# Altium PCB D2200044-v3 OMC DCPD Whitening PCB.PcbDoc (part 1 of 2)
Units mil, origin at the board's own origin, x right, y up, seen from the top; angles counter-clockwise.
Board outline 7000 x 5000 mil, 4 copper layers (Top Layer, Layer 1 (+V), Layer 2 (-V), Bottom Layer), stack 19.156 mil thick; 95 components, 56 nets, 274 pads, 56 vias.
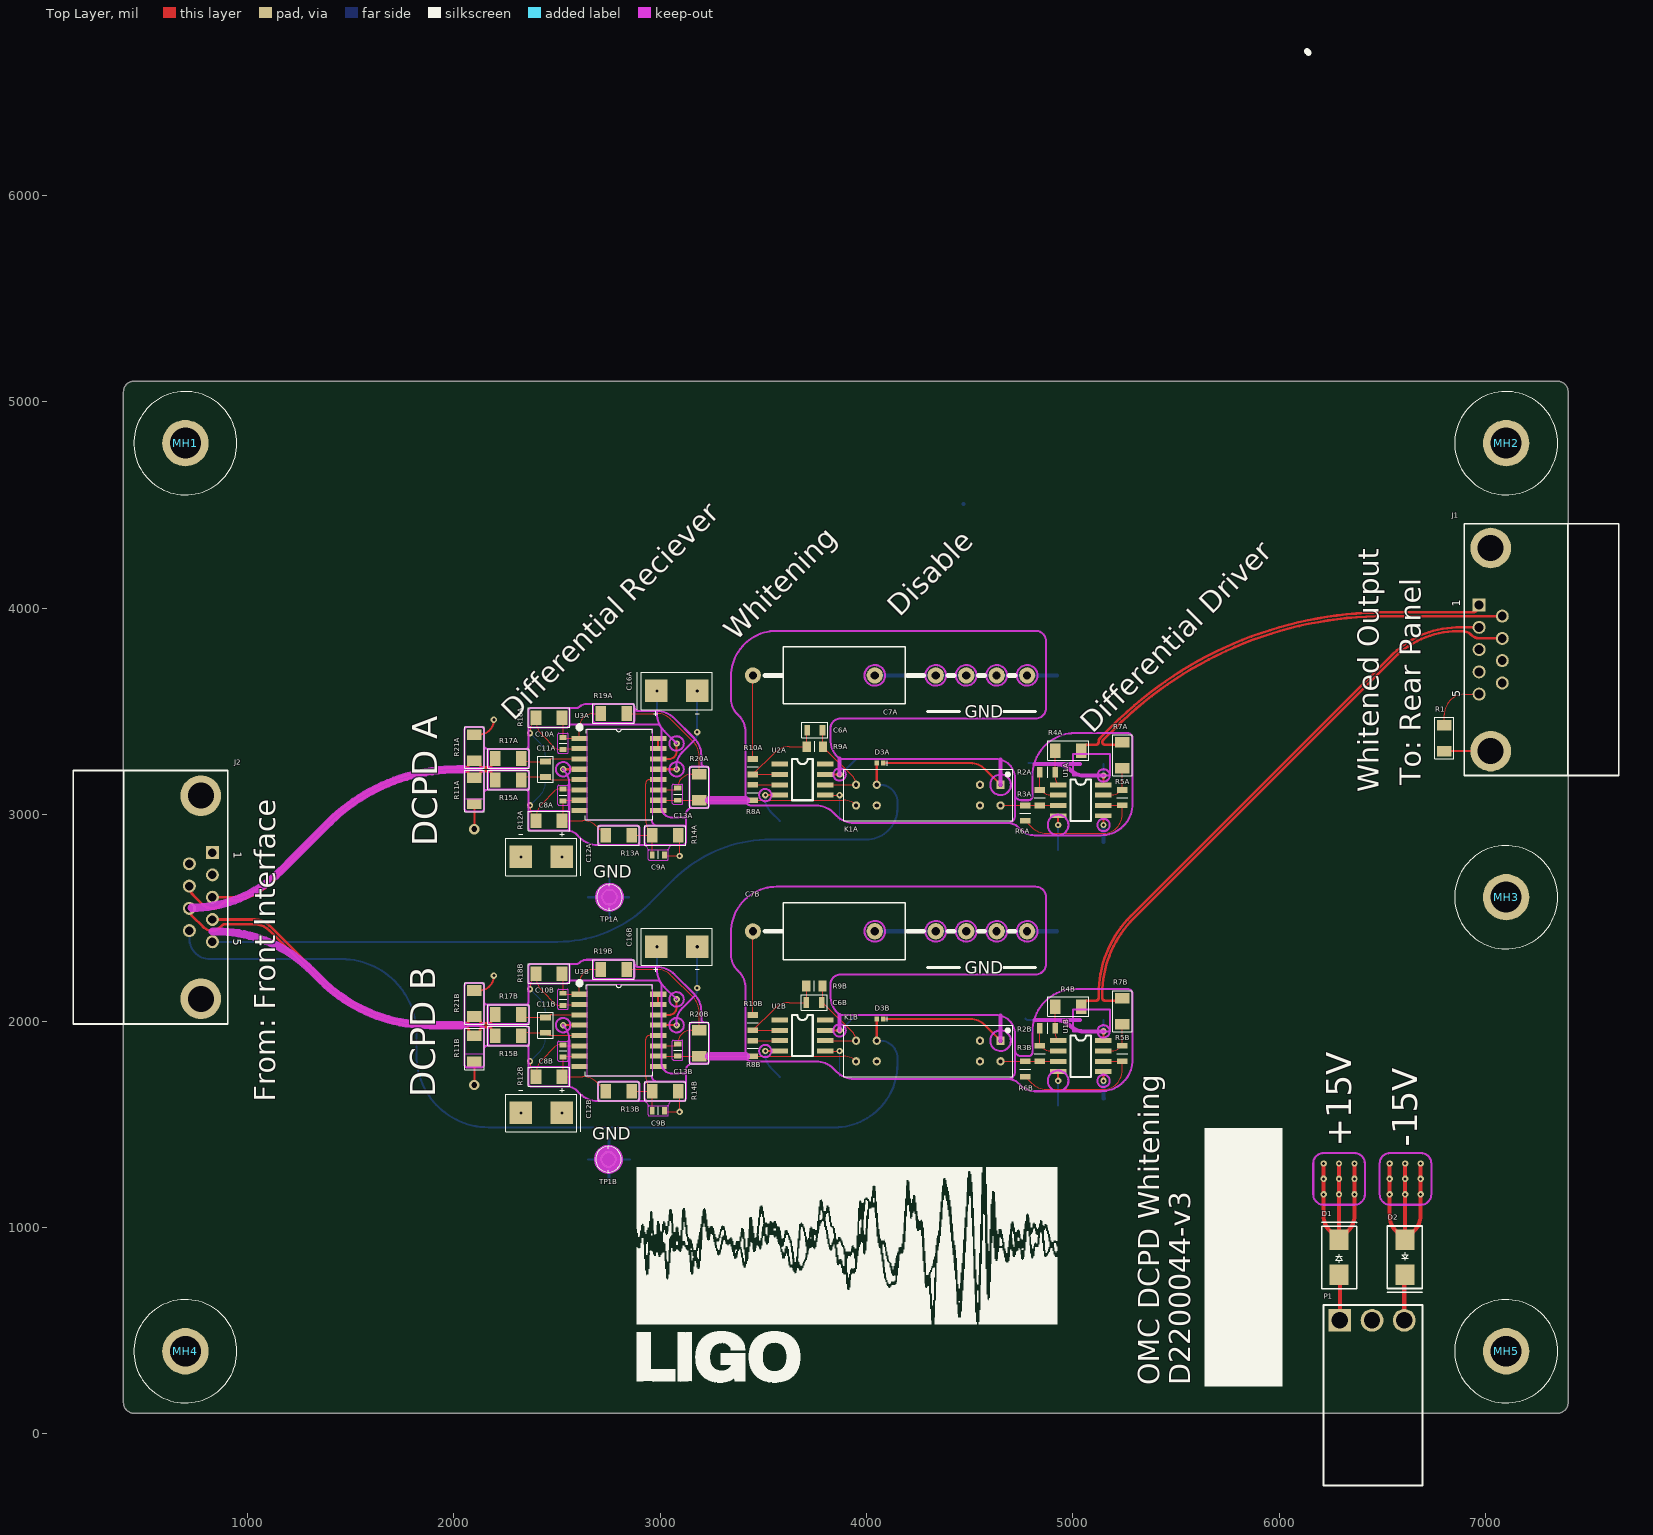
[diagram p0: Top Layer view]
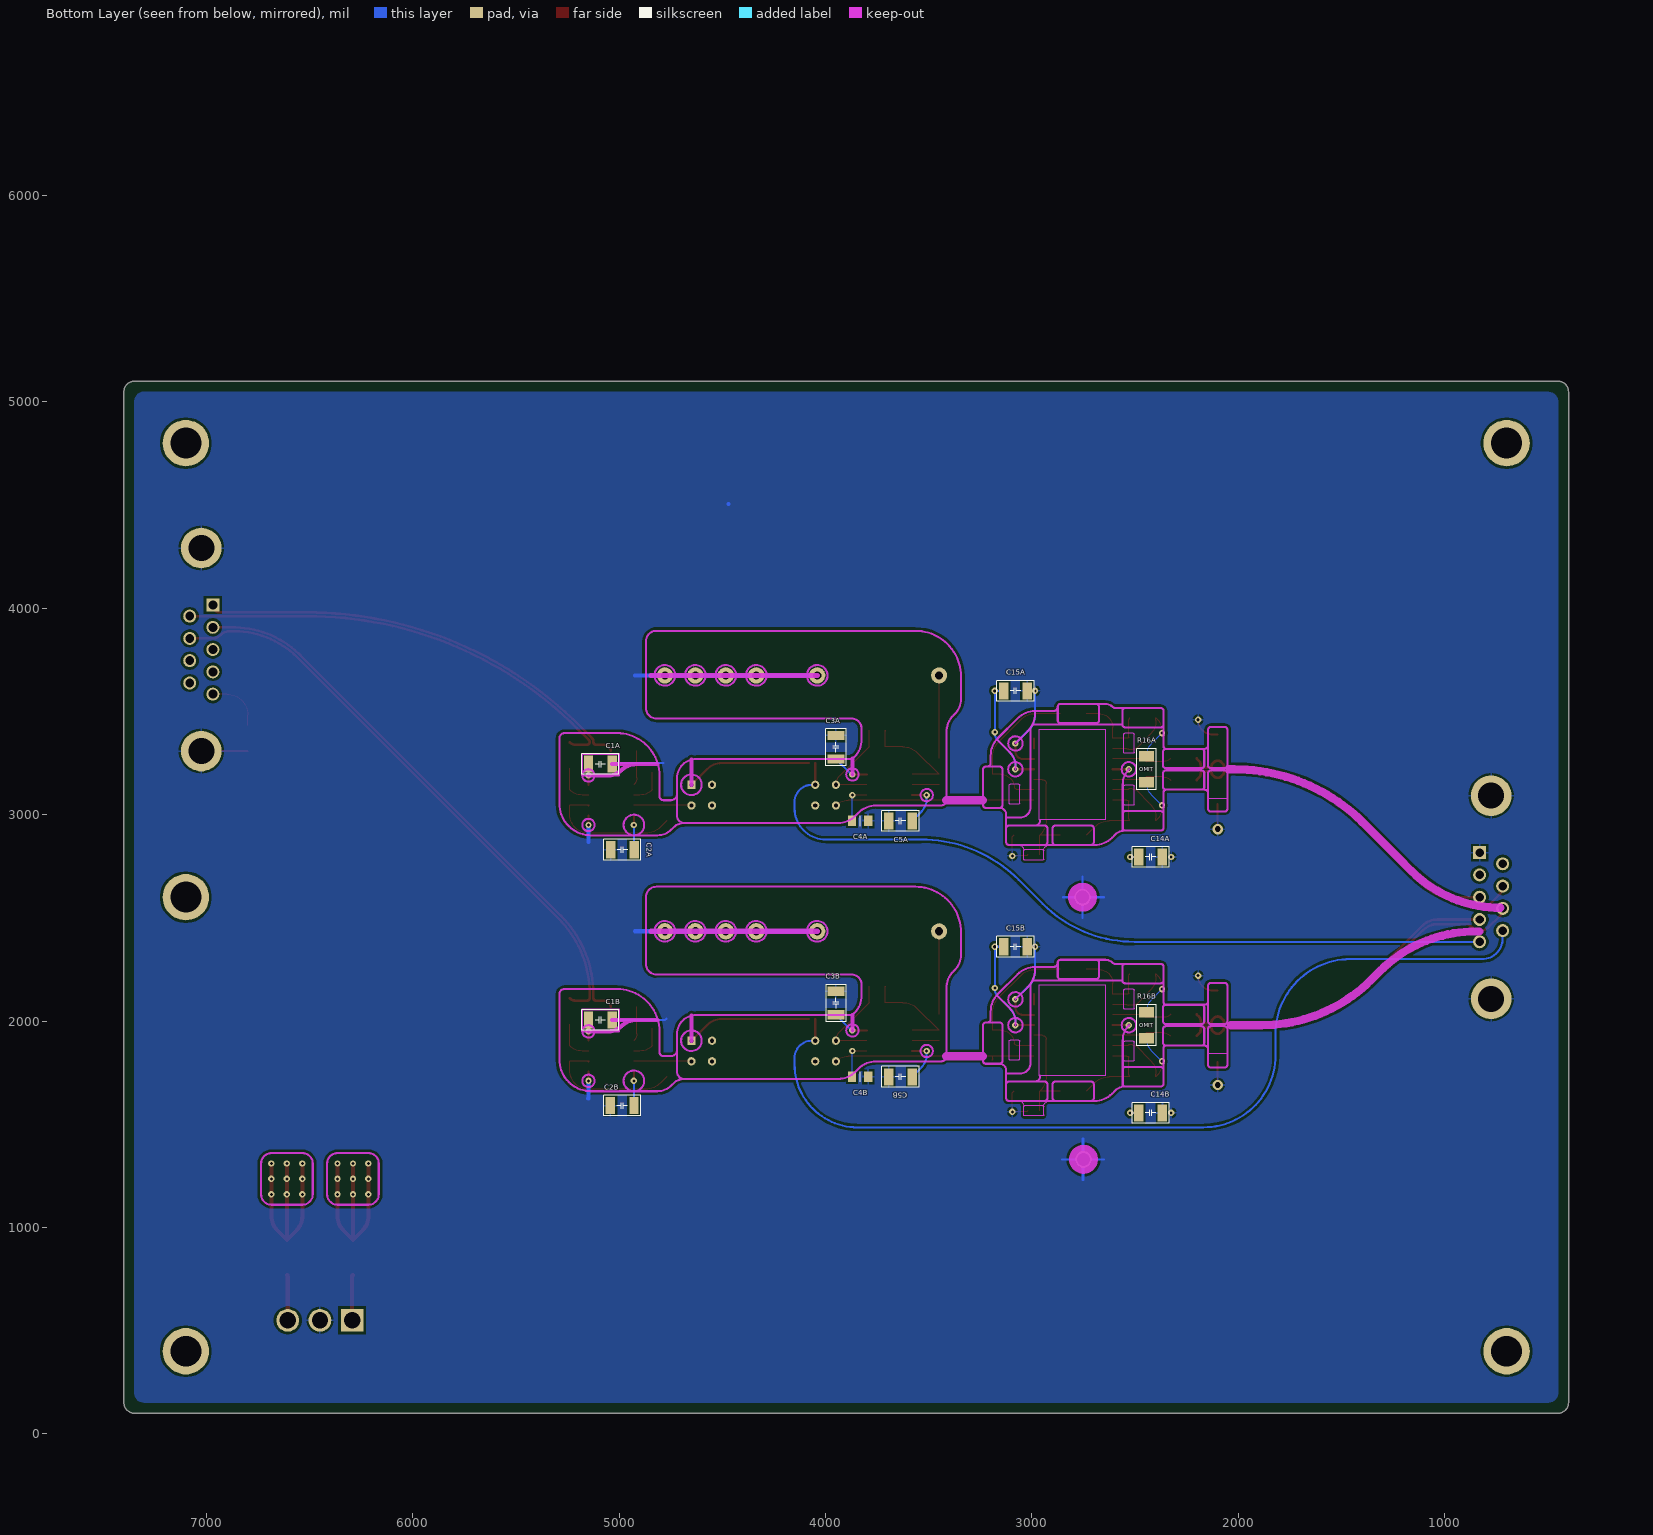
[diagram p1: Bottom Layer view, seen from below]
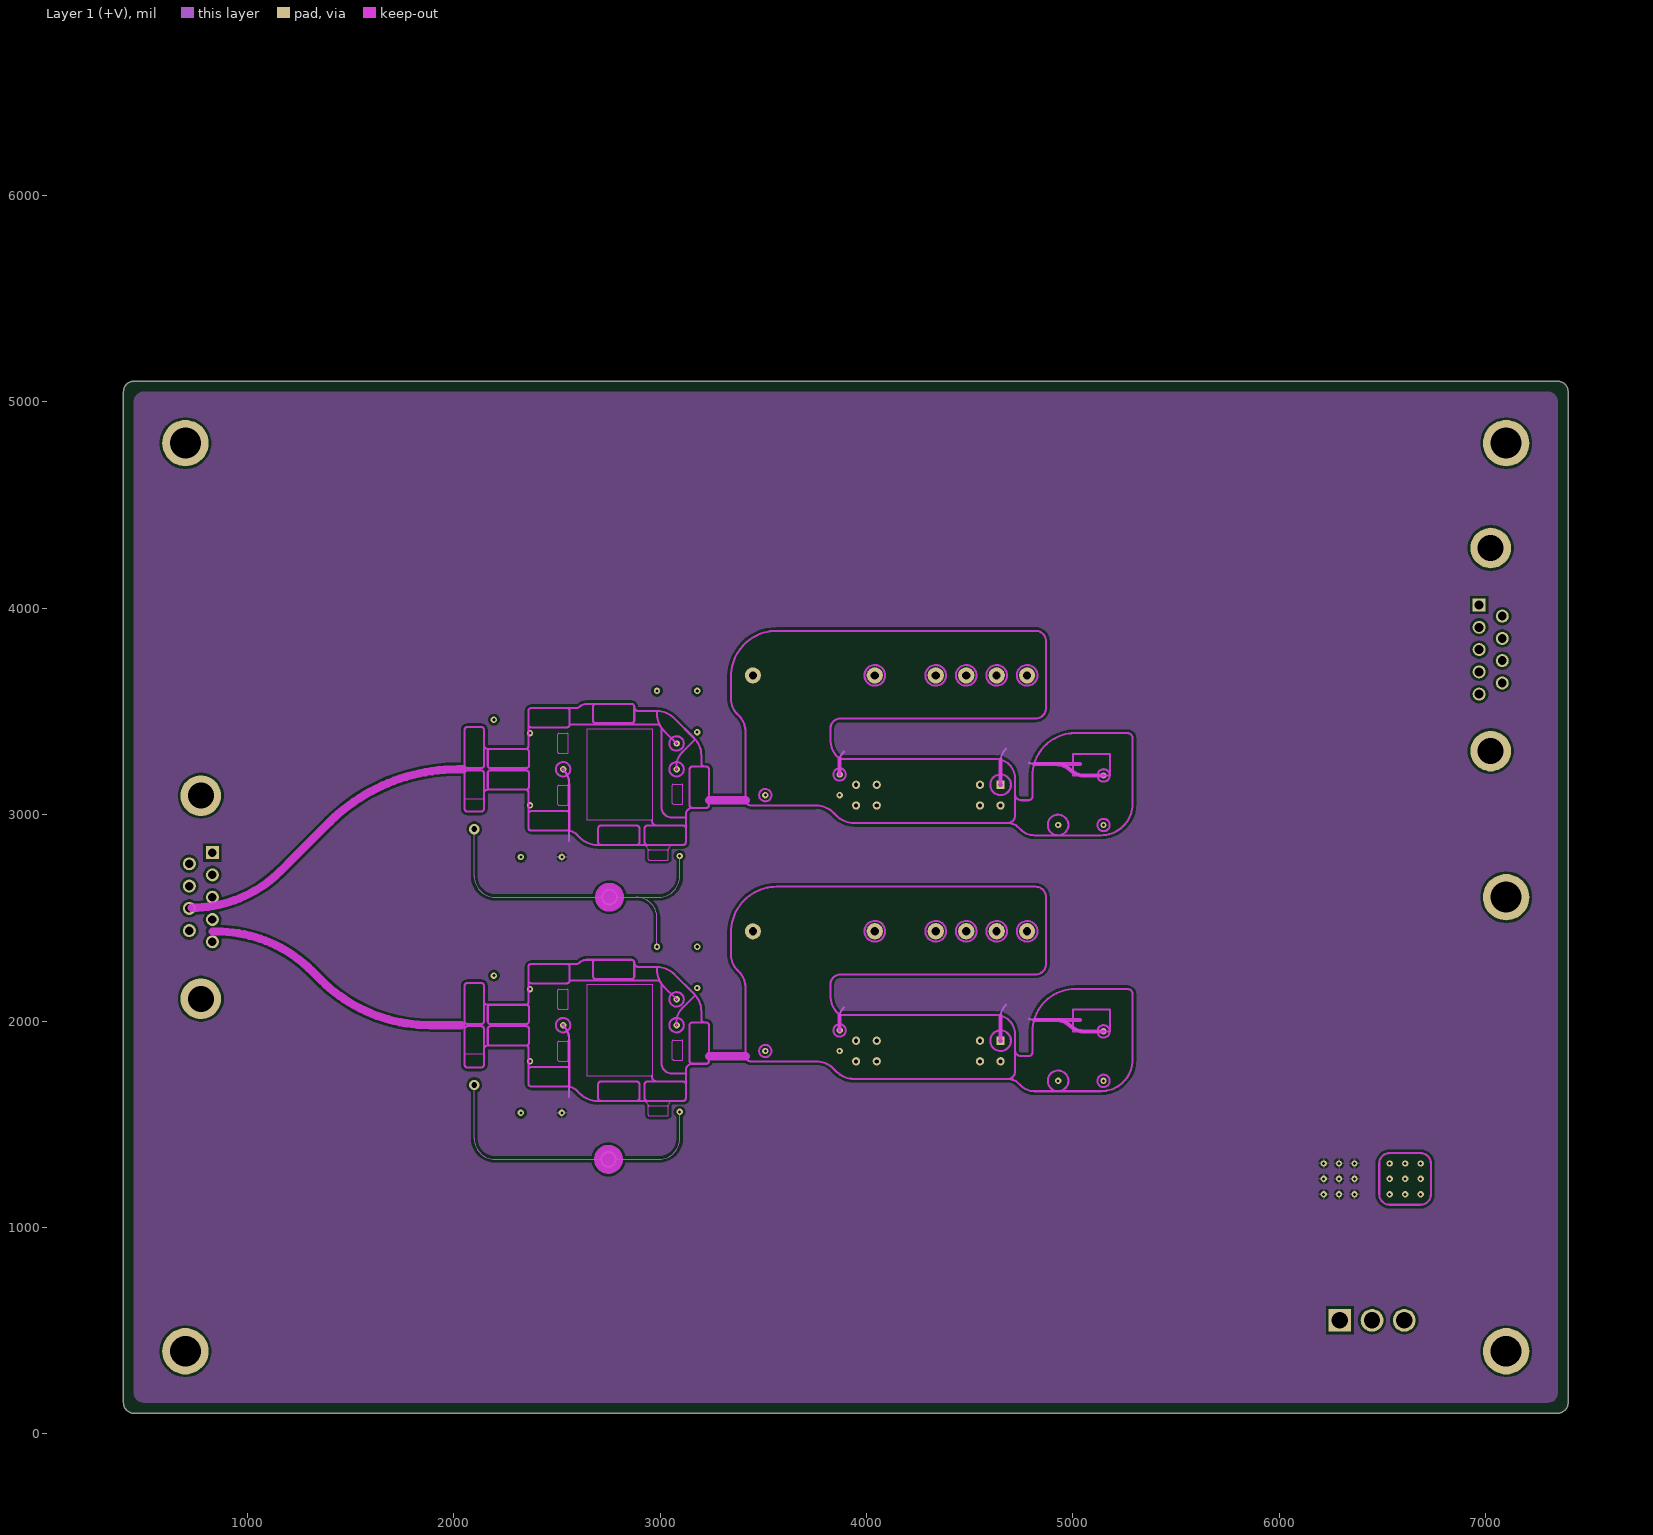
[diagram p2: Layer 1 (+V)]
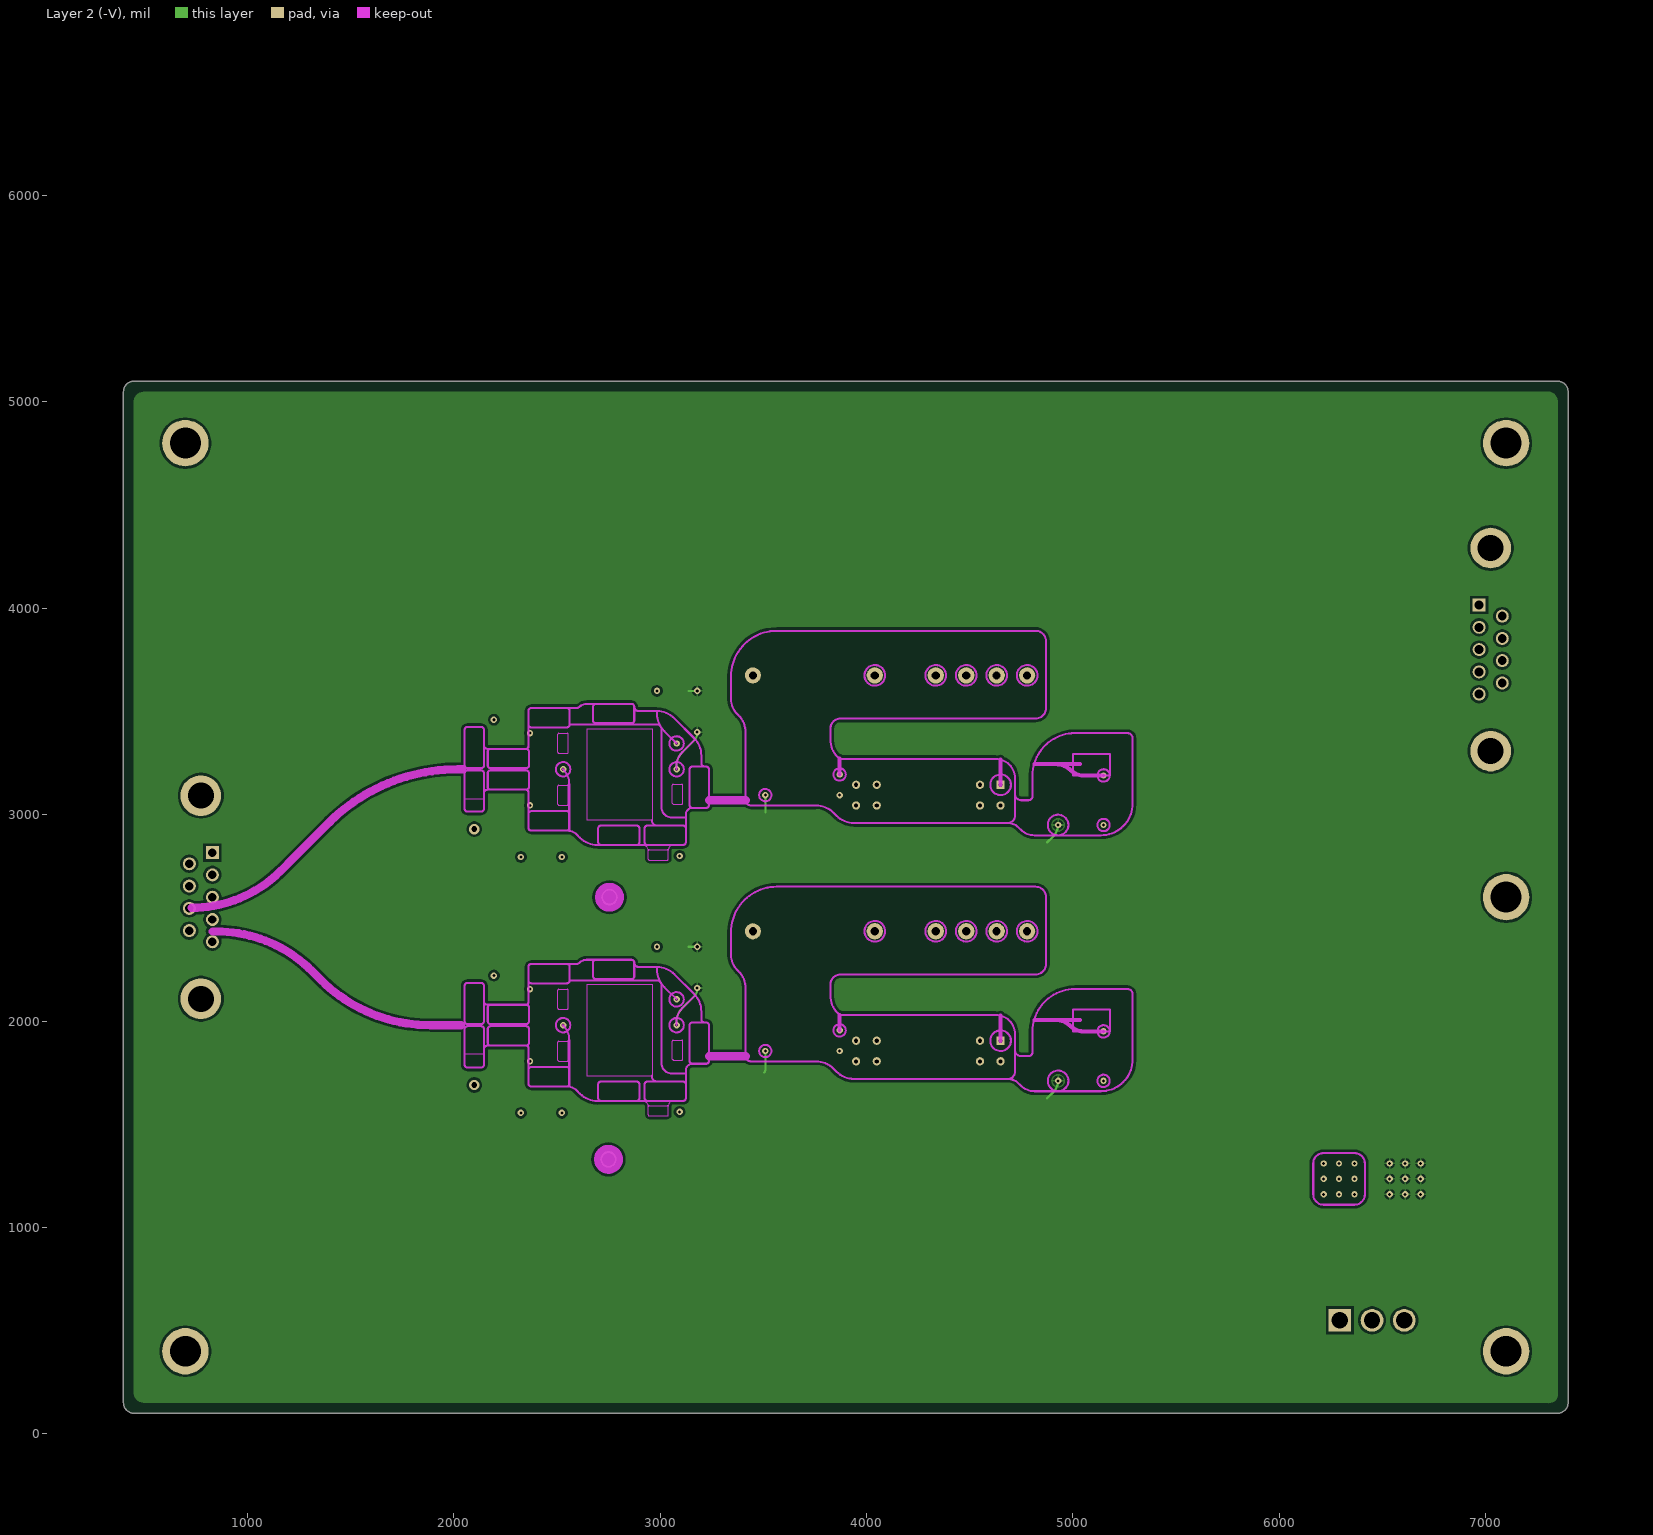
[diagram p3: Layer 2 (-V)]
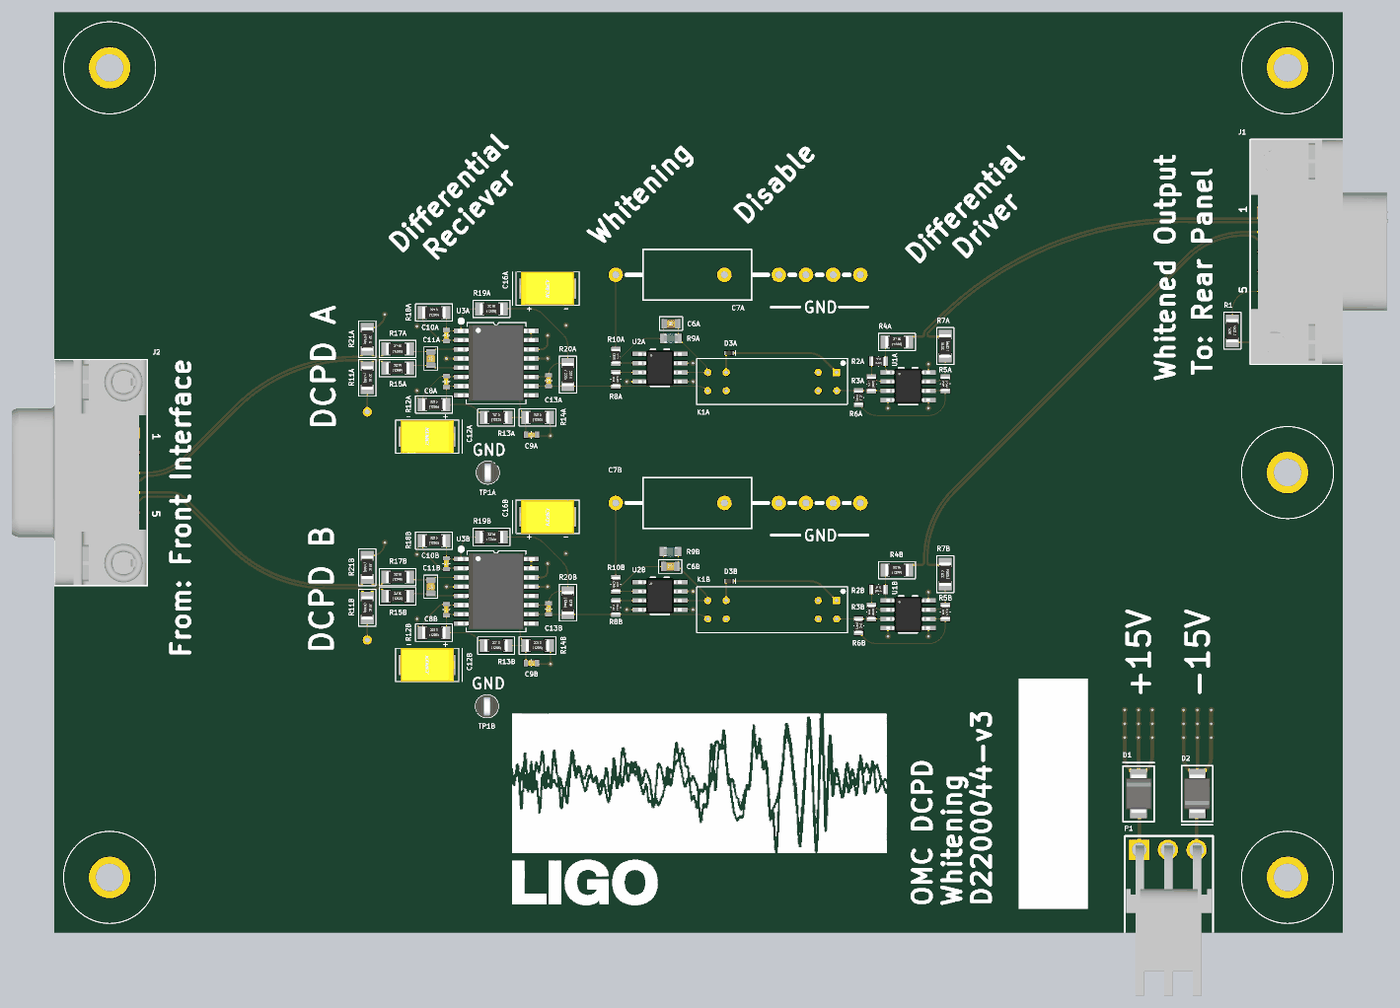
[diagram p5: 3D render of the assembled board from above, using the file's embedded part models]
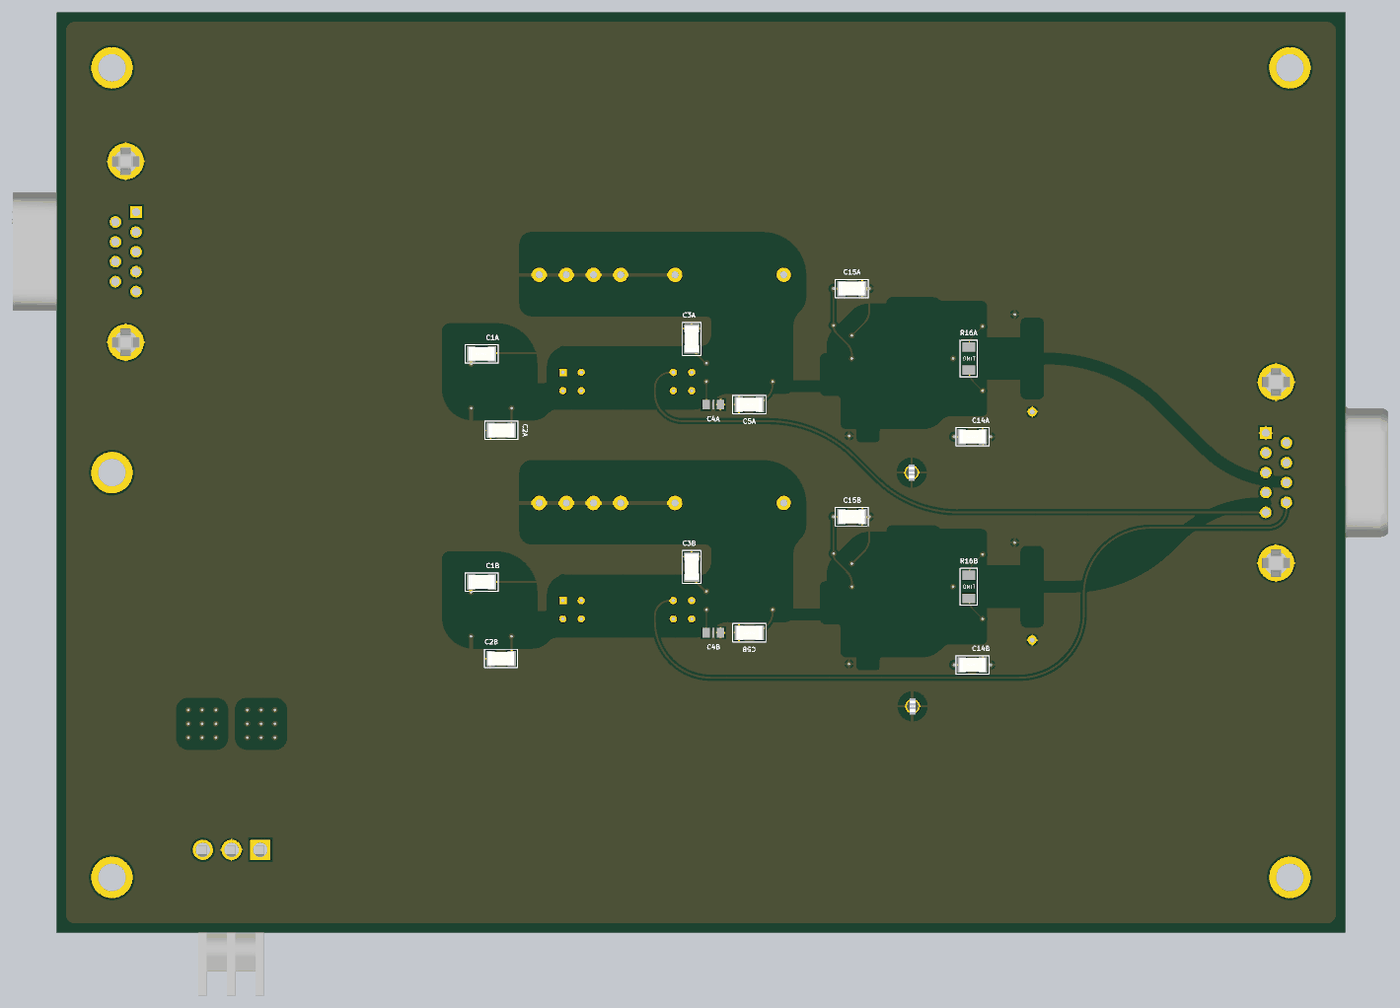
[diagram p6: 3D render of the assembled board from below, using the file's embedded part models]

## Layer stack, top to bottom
Top Solder: solder mask 0.4, Solder Resist, Dk 3.5
Top Layer: signal copper 1.4
Dielectric 2: prepreg 2.8, PP-006, Dk 4.1
Layer 1 (+V): signal copper 1.378
Dielectric 1: core 8, Core-025, Dk 4.6
Layer 2 (-V): signal copper 1.378
Dielectric 3: prepreg 2.8, PP-006, Dk 4.1
Bottom Layer: signal copper 1.4
Bottom Solder: solder mask 0.4, Solder Resist, Dk 3.5

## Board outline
400,5050 cw(c450,5050) 450,5100 7350,5100 cw(c7350,5050) 7400,5050 7400,150 cw(c7350,150) 7350,100 450,100 cw(c450,150) 400,150

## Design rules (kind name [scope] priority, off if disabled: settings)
Clearance [All] p1: gap=2.25 ignorepadtopadclearanceinfootprint=FALSE except(3: Arc-THPad Track-THPad SMDPad-THPad; 5: Arc-Arc Arc-Track Track-Track; 10: SMDPad-Poly; 12: Arc-Fill Arc-Poly Arc-Region Track-Fill Track-Poly Track-Region THPad-Fill THPad-Poly THPad-Region Via-Fill Via-Poly Via-Region Fill-Fill Fill-Poly Fill-Region Poly-Poly Poly-Region Region-Region)
DiffPairsRouting [All] p1: maxlimit=5 minlimit=5 mostfreqgap=5 toplayer_minwidth=12.64 toplayer_maxwidth=12.64 toplayer_prefwidth=12.64 midlayer1_minwidth=9.2 midlayer1_maxwidth=9.2 midlayer1_prefwidth=9.2 midlayer2_minwidth=9.2 midlayer2_maxwidth=9.2 midlayer2_prefwidth=9.2 bottomlayer_minwidth=12.64 bottomlayer_maxwidth=12.64 bottomlayer_prefwidth=12.64 maxuncoupledlength=500
HoleSize [All] p1: absolutevalues=TRUE maxlimit=200 minlimit=14 maxpercent=80.000 minpercent=20.000
MinimumSolderMaskSliver [All] p1: minsoldermaskwidth=3
PlaneConnect [All] p1: planeconnectstyle=Direct reliefexpansion=20 reliefentries=4 reliefconductorwidth=10 reliefairgap=10
PolygonConnect [All] p1: connectstyle=Relief reliefconductorwidth=10 reliefentries=4 polygonreliefangle="90 Angle" airgapwidth=10
RoomDefinition "Whitening B" [InComponentClass('Whitening B')] p1: confinementstyle=ConfineIn formatcopy=TRUE lockcomponents=FALSE outline 2675,1250 2675,1410 2675,1596.72 2936.2,1596.72 3410.41,1596.72 3410.41,2067.23 3676.94,2067.23 3676.94,2129.39 3679.25,2129.39 3679.25,2214.55 4295,2214.55 4295,2295 4455,2295 4455,1992.3 4722.5,1992.3 4722.5,1717.3 3739.59,1717.3 3739.59,1667.3 3739.59,1533.28 3046.87,1533.28 2835,1533.28 2835,1250
RoomDefinition "Whitening A" [InComponentClass('Whitening A')] p2: confinementstyle=ConfineIn formatcopy=TRUE lockcomponents=FALSE outline 2670,2520 2670,2680 2670,2836.72 2936.2,2836.72 3410.41,2836.72 3410.41,3307.23 3674.5,3307.23 3674.5,3459.3 4295,3459.3 4295,3555 4455,3555 4455,3232.3 4722.5,3232.3 4722.5,2957.3 3739.59,2957.3 3739.59,2907.3 3739.59,2773.28 3046.87,2773.28 2830,2773.28 2830,2520
RoomDefinition "Differential-Reciever-Amp D" [InComponentClass('Differential-Reciever-Amp D')] p3: confinementstyle=ConfineIn formatcopy=TRUE lockcomponents=FALSE outline 2020,1610 2020,1770 2040.5,1770 2040.5,2197.5 2349.51,2197.5 2349.51,2289.5 2662.5,2289.5 2662.5,2309.5 2877.5,2309.5 2877.5,2463.05 3264.5,2463.05 3264.5,2227.5 3249.5,2227.5 3249.5,1780.49 3137.5,1780.49 3137.5,1600.5 3046.87,1600.5 3046.87,1533.28 2627.5,1533.28 2627.5,1451.95 2240.5,1451.95 2240.5,1610
RoomDefinition "Differential-Reciever-Amp C" [InComponentClass('Differential-Reciever-Amp C')] p4: confinementstyle=ConfineIn formatcopy=TRUE lockcomponents=FALSE outline 2020,2850 2020,3010 2040.5,3010 2040.5,3437.5 2349.51,3437.5 2349.51,3529.5 2662.5,3529.5 2662.5,3549.5 2877.5,3549.5 2877.5,3703.05 3264.5,3703.05 3264.5,3467.5 3249.5,3467.5 3249.5,3020.49 3137.5,3020.49 3137.5,2840.5 3046.87,2840.5 3046.87,2773.28 2527.5,2773.28 2527.5,2732.5 2322.5,2732.5 2322.5,2850
RoomDefinition "Differential-Driver D" [InComponentClass('Differential-Driver D')] p5: confinementstyle=ConfineIn formatcopy=TRUE lockcomponents=FALSE outline 4730.41,1702.22 4730.41,1832.58 4800.41,1832.58 4800.41,1907.39 4812.22,1907.39 4812.22,2004.59 4865.49,2004.59 4865.49,2129.5 5180.7,2129.5 5180.7,2160.3 5299.7,2160.3 5299.7,1935.3 5279.59,1935.3 5279.59,1777.22 5202.58,1777.22 5202.58,1714.8 5088.17,1714.8 5088.17,1527.5 4883.17,1527.5 4883.17,1702.22
RoomDefinition "Differential-Driver C" [InComponentClass('Differential-Driver C')] p6: confinementstyle=ConfineIn formatcopy=TRUE lockcomponents=FALSE outline 4730.41,2942.22 4730.41,3072.58 4800.41,3072.58 4800.41,3147.39 4812.22,3147.39 4812.22,3244.59 4865.49,3244.59 4865.49,3369.5 5180.7,3369.5 5180.7,3400.3 5299.7,3400.3 5299.7,3175.3 5279.59,3175.3 5279.59,3017.22 5202.58,3017.22 5202.58,2954.8 5087.06,2954.8 5087.06,2767.5 4882.06,2767.5 4882.06,2942.22
RoomDefinition "D2200044-v2 OMC DCPD Whitening" [InComponentClass('D2200044-v2 OMC DCPD Whitening')] p7: confinementstyle=ConfineIn formatcopy=TRUE lockcomponents=FALSE outline 142.95,1971.89 142.95,3228.11 437.5,3228.11 437.5,5062.5 7362.5,5062.5 7362.5,4424.17 7659.02,4424.17 7659.02,3175.83 7362.5,3175.83 7362.5,137.5 6710,137.5 6710,-265 6200,-265 6200,137.5 437.5,137.5 437.5,1971.89
RoutingVias [All] p1: holewidth=28 width=50 viastyle="Through Hole" minholewidth=28 minwidth=50 maxholewidth=28 maxwidth=50
SilkToSilkClearance [All] p1: silktosilkclearance=8
SilkToSolderMaskClearance [IsPad] p1: minsilkscreentomaskgap=2.5 clearancetoexposedcopper=TRUE
SolderMaskExpansion [All] p1: expansion=4 istentingtop=FALSE
Width [All] p1: maxlimit=20 minlimit=5 preferedwidth=10
24 further rules are at their usual default settings.

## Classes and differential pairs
channel class Whitening-v3: "Whitening A" "Whitening B"
channel class Differential-Reciever-Amp: "Differential-Reciever-Amp C" "Differential-Reciever-Amp D"
channel class Differential-Driver: "Differential-Driver C" "Differential-Driver D"
component class "Whitening B": C3B C4B C5B C6B C7B D3B K1B R8B R9B R10B TP1B U2B
component class "Whitening A": C3A C4A C5A C6A C7A D3A K1A R8A R9A R10A TP1A U2A
component class "Differential-Reciever-Amp D": C8B C9B C10B C11B C12B C13B C14B C15B C16B R11B R12B R13B R14B R15B R16B R17B R18B R19B R20B R21B U3B
component class "Differential-Reciever-Amp C": C8A C9A C10A C11A C12A C13A C14A C15A C16A R11A R12A R13A R14A R15A R16A R17A R18A R19A R20A R21A U3A
component class "Differential-Driver D": C1B C2B R2B R3B R4B R5B R6B R7B U1B
component class "Differential-Driver C": C1A C2A R2A R3A R4A R5A R6A R7A U1A
component class "D2200044-v2 OMC DCPD Whitening": D1 D2 J1 J2 MH1 MH2 MH3 MH4 MH5 P1 R1
differential pair "DCPD In B": +"DCPD In B_p" -"DCPD In B_n"
differential pair "DCPD In A": +"DCPD In A_p" -"DCPD In A_n"
differential pair "OMC A - DCPD B": +"OMC A - DCPD B_p" -"OMC A - DCPD B_n"
differential pair "OMC A - DCPD A": +"OMC A - DCPD A_p" -"OMC A - DCPD A_n"

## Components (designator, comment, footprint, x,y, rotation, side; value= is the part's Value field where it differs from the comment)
C1A "0.1 uF" "1206 (3216 Metric) CAP" 5091.5,3245 r180 bottom (schematic designator C1)
C1B "0.1 uF" "1206 (3216 Metric) CAP" 5091.5,2005 r180 bottom (schematic designator C1)
C2A "0.1 uF" "1206 (3216 Metric) CAP" 4984.56,2830 r0 bottom (schematic designator C2)
C2B "0.1 uF" "1206 (3216 Metric) CAP" 4985.67,1590 r0 bottom (schematic designator C2)
C3A "0.1 uF" "1206 (3216 Metric) CAP" 3950,3326.89 r90 bottom (schematic designator C3)
C3B "0.1 uF" "1206 (3216 Metric) CAP" 3950,2086.89 r90 bottom (schematic designator C3)
C4A "0805 OMIT" "2012[0805] - NF" 3832.6,2969.8 r180 bottom (schematic designator C4)
C4B "0805 OMIT" "2012[0805] - NF" 3832.6,1729.8 r180 bottom (schematic designator C4)
C5A "0.1 uF" "1206 (3216 Metric) CAP" 3637.09,2969.8 r0 bottom (schematic designator C5)
C5B "0.1 uF" "1206 (3216 Metric) CAP" 3637.09,1729.8 r0 bottom (schematic designator C5)
C6A "10p +/-0.25pF" "0805 CAP" 3750,3409.8 r0 top (schematic designator C6)
C6B "10p +/-0.25pF" "0805 CAP" 3746.06,2089.8 r0 top (schematic designator C6)
C7A "10uF 1% (PC)" "CAP FILM AXIAL (MULTI LENGTH)" 3892.91,3675 r0 top (schematic designator C7)
C7B "10uF 1% (PC)" "CAP FILM AXIAL (MULTI LENGTH)" 3892.91,2435 r0 top (schematic designator C7)
C8A "4.7 pF (+/-0.05pF)(TF)" "0603 CAP" 2530,3095 r270 top (schematic designator C8)
C8B "4.7 pF (+/-0.05pF)(TF)" "0603 CAP" 2530,1855 r270 top (schematic designator C8)
C9A "4.7 pF (+/-0.05pF)(TF)" "0603 CAP" 2991.54,2805 r0 top (schematic designator C9)
C9B "4.7 pF (+/-0.05pF)(TF)" "0603 CAP" 2991.54,1565 r0 top (schematic designator C9)
C10A "4.7 pF (+/-0.05pF)(TF)" "0603 CAP" 2530,3345 r90 top (schematic designator C10)
C10B "4.7 pF (+/-0.05pF)(TF)" "0603 CAP" 2530,2105 r90 top (schematic designator C10)
C11A "1800pF 50V (1%)(PPS)" "0805 CAP" 2445,3220 r270 top (schematic designator C11)
C11B "1800pF 50V (1%)(PPS)" "0805 CAP" 2445,1980 r270 top (schematic designator C11)
C12A "10uF" "2917 (7343 Metric)" 2425,2795 r0 top (schematic designator C12)
C12B "10uF" "2917 (7343 Metric)" 2425,1555 r0 top (schematic designator C12)
C13A "4.7 pF (+/-0.05pF)(TF)" "0603 CAP" 3085,3099.53 r270 top (schematic designator C13)
C13B "4.7 pF (+/-0.05pF)(TF)" "0603 CAP" 3085,1859.53 r270 top (schematic designator C13)
C14A "0.1 uF" "1206 (3216 Metric) CAP" 2425,2795 r180 bottom (schematic designator C14)
C14B "0.1 uF" "1206 (3216 Metric) CAP" 2425,1555 r180 bottom (schematic designator C14)
C15A "0.1 uF" "1206 (3216 Metric) CAP" 3080,3600 r180 bottom (schematic designator C15)
C15B "0.1 uF" "1206 (3216 Metric) CAP" 3080,2360 r180 bottom (schematic designator C15)
C16A "10uF" "2917 (7343 Metric)" 3080,3600 r180 top (schematic designator C16)
C16B "10uF" "2917 (7343 Metric)" 3080,2360 r180 top (schematic designator C16)
D1 "50V 1A" "DO-214AA, SMB" 6290,855 r90 top
D2 "50V 1A" "DO-214AA, SMB" 6610,855 r270 top
D3A "1N4148" "0402 Diode" 4065.75,3249.8 r0 top (schematic designator D3)
D3B "1N4148" "0402 Diode" 4065.75,2009.8 r0 top (schematic designator D3)
J1 "D9F RA" "D9F 90DEG" 7025,3800 r90 top
J2 "D9M 90DEG" "D9M 90DEG" 775,2600 r270 top locked
K1A "Relay SPDT" "Relay SPDT 0.25A 12V" 4300,3094.8 r180 top (schematic designator K1)
K1B "Relay SPDT" "Relay SPDT 0.25A 12V" 4300,1854.8 r180 top (schematic designator K1)
MH1 "Mounting Hole #6" "Mounting Hole #6" 700,4800 r0 top
MH2 "Mounting Hole #6" "Mounting Hole #6" 7100,4800 r0 top
MH3 "Mounting Hole #6" "Mounting Hole #6" 7100,2600 r0 top
MH4 "Mounting Hole #6" "Mounting Hole #6" 700,400 r0 top
MH5 "Mounting Hole #6" "Mounting Hole #6" 7100,400 r0 top
P1 "HDR 3x1 R/A" "MOLEX HDR1X3 R/A" 6450,550 r0 top locked
R1 "0 Ohm" "1206 Resistor" 6800,3370.99 r90 top
R2A "5k (0.05%)" "0805 Resistor" 4877.4,3205 r0 top (schematic designator R2)
R2B "5k (0.05%)" "0805 Resistor" 4877.4,1965 r0 top (schematic designator R2)
R3A "5k (0.05%)" "0805 Resistor" 4840,3082.2 r90 top (schematic designator R3)
R3B "5k (0.05%)" "0805 Resistor" 4840,1842.2 r90 top (schematic designator R3)
R4A "0 Ohm" "1206 Resistor" 4977.99,3310 r0 top (schematic designator R4)
R4B "0 Ohm" "1206 Resistor" 4977.99,2070 r0 top (schematic designator R4)
R5A "5k (0.05%)" "0805 Resistor" 5240,3082.4 r90 top (schematic designator R5)
R5B "5k (0.05%)" "0805 Resistor" 5240,1842.4 r90 top (schematic designator R5)
R6A "5k (0.05%)" "0805 Resistor" 4770,3007.4 r270 top (schematic designator R6)
R6B "5k (0.05%)" "0805 Resistor" 4770,1767.4 r270 top (schematic designator R6)
R7A "0 Ohm" "1206 Resistor" 5240.2,3287.8 r90 top (schematic designator R7)
R7B "0 Ohm" "1206 Resistor" 5240.2,2047.8 r90 top (schematic designator R7)
R8A "1k (0.01%)" "0805 Resistor" 3450,3107.4 r90 top (schematic designator R8)
R8B "1k (0.01%)" "0805 Resistor" 3450,1867.4 r90 top (schematic designator R8)
R9A "14.3k (0.1%)" 2012[0805] 3750,3329.8 r0 top (schematic designator R9)
R9B "14.3k (0.1%)" 2012[0805] 3748.03,2169.8 r0 top (schematic designator R9)
R10A "1.6k (0.05%)" "0805 Resistor" 3450,3232.2 r270 top (schematic designator R10)
R10B "1.6k (0.05%)" "0805 Resistor" 3450,1992.2 r270 top (schematic designator R10)
R11A "100k (0.01%)" "1206 Resistor" 2100,3115 r270 top (schematic designator R11)
R11B "100k (0.01%)" "1206 Resistor" 2100,1865.01 r270 top (schematic designator R11)
R12A "1k (0.01%)" "1206 Resistor" 2462.01,2970 r0 top (schematic designator R12)
R12B "1k (0.01%)" "1206 Resistor" 2462.01,1730 r0 top (schematic designator R12)
R13A "3.01k (0.01%)" "1206 Resistor" 2800,2900 r0 top (schematic designator R13)
R13B "3.01k (0.01%)" "1206 Resistor" 2800,1660 r0 top (schematic designator R13)
R14A "1.5k (0.01%)" "1206 Resistor" 3025,2900 r0 top (schematic designator R14)
R14B "1.5k (0.01%)" "1206 Resistor" 3025,1660 r0 top (schematic designator R14)
R15A "1k (0.01%)" "1206 Resistor" 2265,3168 r0 top (schematic designator R15)
R15B "1k (0.01%)" "1206 Resistor" 2265,1928 r0 top (schematic designator R15)
R16A "OMIT" "1206 Resistor - OMIT" 2445,3220 r270 bottom (schematic designator R16)
R16B "OMIT" "1206 Resistor - OMIT" 2445,1980 r270 bottom (schematic designator R16)
R17A "1k (0.01%)" "1206 Resistor" 2265,3272 r0 top (schematic designator R17)
R17B "1k (0.01%)" "1206 Resistor" 2265,2032 r0 top (schematic designator R17)
R18A "1k (0.01%)" "1206 Resistor" 2462.01,3470 r0 top (schematic designator R18)
R18B "1k (0.01%)" "1206 Resistor" 2462.01,2230 r0 top (schematic designator R18)
R19A "3.01k (0.01%)" "1206 Resistor" 2775,3490 r0 top (schematic designator R19)
R19B "3.01k (0.01%)" "1206 Resistor" 2775,2250 r0 top (schematic designator R19)
R20A "1.5k (0.01%)" "1206 Resistor" 3190,3132.99 r270 top (schematic designator R20)
R20B "1.5k (0.01%)" "1206 Resistor" 3190,1892.99 r270 top (schematic designator R20)
R21A "100k (0.01%)" "1206 Resistor" 2100,3325 r270 top (schematic designator R21)
R21B "100k (0.01%)" "1206 Resistor" 2100,2085 r270 top (schematic designator R21)
TP1A "Black" "Test Point Tall - Black" 2755,2600 r0 top (schematic designator TP1)
TP1B "Black" "Test Point Tall - Black" 2750,1330 r0 top (schematic designator TP1)
U1A "AD8672" "SOIC-8 (0.154\", 3.90mm Width)" 5038.58,3069.8 r0 top (schematic designator U1)
U1B "AD8672" "SOIC-8 (0.154\", 3.90mm Width)" 5038.58,1829.8 r0 top (schematic designator U1)
U2A "OP37" "SOIC-8 (0.154\", 3.90mm Width)" 3690,3169.8 r0 top (schematic designator U2)
U2B "OP37" "SOIC-8 (0.154\", 3.90mm Width)" 3690,1929.8 r0 top (schematic designator U2)
U3A "LT1125CS" "SOIC-16W (0.295\", 7.50mm Width)" 2800,3195 r0 top (schematic designator U3)
U3B "LT1125CS" "SOIC-16W (0.295\", 7.50mm Width)" 2800,1955 r0 top (schematic designator U3)

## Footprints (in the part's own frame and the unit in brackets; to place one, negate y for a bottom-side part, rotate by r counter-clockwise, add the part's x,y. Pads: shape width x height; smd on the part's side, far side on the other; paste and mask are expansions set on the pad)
"0402 Diode" [mm]
  rect 0.5x0.6 smd: 1(-0.4,0) 2(0.4,0)
  silkscreen extent 0.89,-0.3 0.89,0.3, body extent -0.5,-0.3 0.5,0.3, height 0.5
"0603 CAP" [mm]
  rect 0.6x0.9 smd: 1(-0.75,0) 2(0.75,0)
  silkscreen extent 0,-0.48 0,0.48, body extent -0.8,-0.4 0.8,0.4, height 0.8
"0805 CAP" [mm]
  rect 0.7x1.3 smd: 1(-0.95,0) 2(0.95,0)
  silkscreen extent -1.6,-0.94 1.6,0.94, body extent -1,-0.62 1,0.63, height 0.9
"0805 Resistor" [mm]
  rect 0.7x1.3 smd: 1(-0.95,0) 2(0.95,0)
  silkscreen extent 0,-0.69 0,0.69, body extent -1,-0.62 1,0.63, height 0.45
"1206 (3216 Metric) CAP" [mm] "Chip Capacitor; Body 3.2 x 1.6 mm (LxW typ)"
  rect 1.15x2.1 smd: 1(-1.45,0) 2(1.45,0)
  silkscreen extent -2.29,-1.27 2.29,1.27, body extent -1.8,-0.93 1.8,0.97, height 1.11
"1206 Resistor" [mm]
  rect 1.3x1.8 smd: 1(-1.6,0) 2(1.6,0)
  silkscreen extent -2.54,-1.19 2.54,1.19, body extent -1.6,-0.8 1.6,0.8, height 0.55
"1206 Resistor - OMIT" [mm]
  rect 1.3x1.8 smd: 1(-1.6,0) 2(1.6,0)
  silkscreen extent -2.54,-1.19 2.54,1.19
2012[0805] [mm] "Chip Resistor; Body 2.0 x 1.3 mm (LxW typ)"
  rect 1x1.3 smd: 1(-1,0) 2(1,0)
  silkscreen extent 0,-0.64 0,0.64, body extent -1,-0.62 1,0.63, height 0.46
"2012[0805] - NF" [mm] "Chip Resistor; Body 2.0 x 1.3 mm (LxW typ)"
  rect 1x1.3 smd: 1(-1,0) 2(1,0)
  silkscreen extent 0,-0.64 0,0.64
"2917 (7343 Metric)" [mm]
  rect 2.77x2.77 smd: 1(2.528,0) 2(-2.527,0)
  silkscreen extent -4.37,-2.3 4.83,3.05, body extent -3.8,-2.3 3.8,2.3, height 4.31
"CAP FILM AXIAL (MULTI LENGTH)" [mil]
  round 78 hole 39.37: 1(-442.91,0)
  round 79 hole 39.37: 2(147.64,0) 2(442.91,0) 2(590.55,0) 2(738.19,0) 2(885.83,0)
  silkscreen extent -384,-138 827,138, body extent -276,-128 276,128, height 285
"D9F 90DEG" [mm]
  rect 1.6x1.6 hole 1.1: 1(5.486,1.422)
  round 1.6 hole 1.1: 2(2.743,1.422) 3(0,1.422) 4(-2.743,1.422) 5(-5.486,1.422) 6(4.115,-1.422) 7(1.372,-1.422) 8(-1.365,-1.422) 9(-4.115,-1.422)
  round 5 hole 3.2: 10(-12.497,0) 11(12.497,0)
  silkscreen extent -15.5,-15.75 15.5,3.25, body extent -15.49,-15.71 15.49,3.18, height 12.56
"D9M 90DEG" [mm]
  rect 1.6x1.6 hole 1.04: 1(-5.486,1.422)
  round 1.6 hole 1.04: 2(-2.743,1.422) 3(0,1.422) 4(2.743,1.422) 5(5.486,1.422) 6(-4.115,-1.422) 7(-1.372,-1.422) 8(1.372,-1.422) 9(4.115,-1.422)
  round 5 hole 3.2: 10(-12.497,0) 11(12.497,0)
  silkscreen extent -15.6,-15.7 15.6,3.3, body extent -15.52,-15.4 15.51,3.2, height 12.56
"DO-214AA, SMB" [mm]
  rect 2.5x2.3 smd: 1(-2.15,0) 2(2.15,0)
  silkscreen extent -3.86,-2.18 4.32,2.13, body extent -2.7,-1.83 2.7,1.77, height 2.32
"MOLEX HDR1X3 R/A" [mil]
  rect 110x110 hole 79: 1(-156,0)
  round 110 hole 79: 2(0,0) 3(156,0)
  silkscreen extent -235,-800 245,75, body extent -226,-793 236,23, height 394
"Mounting Hole #6" [mil]
  round 225 hole 150: 1(0,0)
  silkscreen extent -250,-250 250,250
"Relay SPDT 0.25A 12V" [mil] "RELAY REED SPDT 250MA 12V"
  rect 40x40 hole 20: 1(-350,-50)
  round 40 hole 20: 2(-250,-50) 3(250,-50) 4(350,-50) 5(350,50) 6(250,50) 7(-250,50) 8(-350,50)
  silkscreen extent -410,-125 410,125, body extent -410,-125 410,125, height 300
"SOIC-8 (0.154\", 3.90mm Width)" [mil] "Small Outline 8-pin IC"
  rect 80x24 smd: 1(-110,75) 2(-110,25) 3(-110,-25) 4(-110,-75) 5(110,-75) 6(110,-25) 7(110,25) 8(110,75)
  silkscreen extent -50,-100 50,100, body extent -118,-96 118,96, height 67
"SOIC-16W (0.295\", 7.50mm Width)" [mm]
  rect 2x0.63 smd: 1(-4.85,4.445) 2(-4.85,3.175) 3(-4.85,1.905) 4(-4.85,0.635) 5(-4.85,-0.635) 6(-4.85,-1.905) 7(-4.85,-3.175) 8(-4.85,-4.445) 9(4.85,-4.445) 10(4.85,-3.175) 11(4.85,-1.905) 12(4.85,-0.635) 13(4.85,0.635) 14(4.85,1.905) 15(4.85,3.175) 16(4.85,4.445)
  silkscreen extent -5.07,-5.59 4.13,6.05, body extent -5.31,-5.25 5.31,5.25, height 2.66
"Test Point Tall - Black" [mil] "Test Point Tall Black"
  round 80 hole 63: 1(0,0)
  Keep-Out Layer circle w70: c0,0 r35
  silkscreen extent -62,-62 62,62, body extent -63,-62 62,63, height 321

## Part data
C1A C1B C2A C2B C3A C3B C5A C5B C14A C14B C15A C15B: library part "0.1 uF 5% (1206)", "Multilayer Ceramic Capacitor, C Series, 0.1 - F, - 5%, C0G / NP0, 50 V, 1210 [3225 Metric] ;RoHS Compliant: Yes", Capacitance=100nF, Case Code (Imperial)=1210, Case Code (Metric)=3225, Dielectric=C0G, Dielectric Material=Ceramic, Manufacturer=KEMET, Manufacturer Part Number=C1210C104J5GACTU, Max Operating Temperature=125°C, Min Operating Temperature=-55°C, Package Quantity=2500, Supplier Part Number 1=399-11187-1-ND, Temperature Coefficient=30ppm/°C, Tolerance=5%, Voltage Rating=50V
C6A C6B: library part "10pF 50V +/-0.25pF (0805)", "Cap Ceramic 10pF 50V C0G 0.25pF SMD 0805 125°C Paper T/R", Capacitance=10pF, Case/Package=0805, Dielectric=C0G, Dielectric Material=Ceramic, Manufacturer=KEMET, Manufacturer Part Number=C0805C100C5GAC7800, Max Operating Temperature=125°C, Min Operating Temperature=-55°C, Supplier Part Number 1=399-C0805C100C5GAC7800CT-ND, Voltage Rating (DC)=50V
C7A C7B: library part "10uF 50V 1% (PC)", "Metallized Polycarbonate Wrap and Fill Tubular Configuration"
C8A C8B C9A C9B C10A C10B C13A C13B: library part "4.7 pF +/- 0.05pF (0603)", "SMD Microwave Thin-Film Chip Capacitors 0603 4.7pF 50volts C0G +/-0.05pF", Capacitance=4.7pF, Case Code (Imperial)=0603, Case Code (Metric)=1608, Dielectric=C0G, Manufacturer="Kyocera AVX", Manufacturer Part Number=06035J4R7ABTTR, Max Operating Temperature=125°C, Min Operating Temperature=-55°C, Package Quantity=3000, Resistor Type="Thin Film", Supplier Part Number 1=478-10811-1-ND, Voltage Rating=50V
C11A C11B: library part "1800 pF 50V 1% (0805) PPS Film", "Capacitor; ECHU, SMD, Stack Met PPS Film Cap, 50VDC, 0.0018uF, 2%, 0805, Cut Tape", Capacitance=1.8nF, Case Code (Imperial)=0805, Case Code (Metric)=2012, Dielectric=PPS, Dielectric Material=Polyphenylene, Insulation Resistance=3GR, Manufacturer=Panasonic, Manufacturer Part Number=ECH-U1H182GX5, Max Operating Temperature=125°C, Min Operating Temperature=-55°C, Package Quantity=3000, Supplier Part Number 1=PCF1299CT-ND, Tolerance=2%, Voltage=50V
C12A C12B C16A C16B: library part "10uF Tant 10% 35V (2917)", "10µF Molded Tantalum Capacitors 35V 2917 (7343 Metric) 125mOhm", Case Code (Imperial)=2917, Case Code (Metric)=7343, ESR (Equivalent Series Resistance)=125mR, Manufacturer=KEMET, Manufacturer Part Number=T495D106K035ATE125, Max Operating Temperature=125°C, Min Operating Temperature=-55°C, Package Quantity=1, Supplier Part Number 1=399-10292-1-ND, Tolerance=10%, Voltage Rating=35V
D1 D2: library part "Diode 50V 1A SMB", "DIODE GEN PURP 50V 1A SMB", Average Rectified Current=1A, Capacitance=10pF, Case/Package=SMB, Forward Voltage=1.1V, Manufacturer=Diodes, Manufacturer Part Number=S1AB-13-F, Max Operating Temperature=150°C, Max Repetitive Reverse Voltage (Vrrm)=50V, Max Surge Current=30A, Min Operating Temperature=-65°C, Package Quantity=3000, Peak Reverse Current=5uA, Supplier Part Number 1=S1AB-FDICT-ND
D3A D3B: library part "Diode 1N4148 0402", "Diode Standard 100V 150mA Surface Mount DFN1006-2", Average Rectified Current=150mA, Manufacturer=MCC, Manufacturer Part Number=1N4148WL2-TP, Max Reverse Voltage (DC)=100V, Supplier Part Number 1=1N4148WL2-TPMSCT-ND
J1: library part "D9F 90DEG", "9 Position D-Sub Receptacle, Female Sockets Connector", Case/Package=Metal, Color=Black, Current Rating=6A, Flammability Rating="UL94 V-0", Manufacturer="TE Connectivity", Manufacturer Part Number=5747844-4, Max Operating Temperature=105°C, Min Operating Temperature=-55°C, Package Quantity=130, Supplier Part Number 1=A32117-ND, Voltage Rating=125V
J2: "9 Position D-Sub Plug, Male Pins Connector", Color=Black, Current Rating=5A, Manufacturer=EDAC, Manufacturer Part Number=621-009-260-042, Max Operating Temperature=105°C, Min Operating Temperature=-55°C, Package Quantity=25, Supplier Part Number 1=621-009-260-042-ND
K1A K1B: library part "Relay SPDT 12V 0.25A", "RELAY REED SPDT .25A 12V", Coil Current=8mA, Coil Power=96mW, Coil Resistance=1.5kR, Coil Voltage (DC)=12V, Contact Current Rating=250mA, Manufacturer=Comus, Manufacturer Part Number=BFM-1C-12E, Max Operating Temperature=85°C, Min Operating Temperature=-25°C, Supplier Part Number 1=1835-1150-ND
P1: library part "MOLEX HDR 3x1 R/A", "Connector Header Through Hole, Right Angle 3 position 0.156\" (3.96mm)", Color=Natural, Contact Resistance=10mR, Housing Color=White, Manufacturer=Molex, Manufacturer Part Number=0417920512, Max Operating Temperature=75°C, Min Operating Temperature=0°C, Package Quantity=600, Supplier Part Number 1=WM13208-ND
R1 R4A R4B R7A R7B: library part "0 Ohm (1206)", "RES 0 OHM JUMPER 1/4W 1206", Case Code (Imperial)=1206, Case Code (Metric)=3216, Current Rating=2A, Manufacturer="Stackpole Electronics", Manufacturer Part Number=RMCF1206ZT0R00, Max Operating Temperature=155°C, Max Power Dissipation=250mW, Min Operating Temperature=-55°C, Resistance=0mR, Resistor Type="Thick Film", Supplier Part Number 1=RMCF1206ZT0R00CT-ND, Working Voltage=200V
R2A R2B R3A R3B R5A R5B R6A R6B: library part "5k Ohm 0.05% (0805)", "Res Thin Film 0805 5K Ohm 0.05% 1/4W ±5ppm/°C Molded SMD SMD T/R", Case Code (Imperial)=0805, Case Code (Metric)=2012, Manufacturer="Vishay Dale Thin Film", Manufacturer Part Number=PLT0805Z5001AST5, Max Operating Temperature=125°C, Max Power Dissipation=250mW, Min Operating Temperature=-55°C, Package Quantity=1, Resistance=5kR, Resistor Type="Thin Film", Supplier Part Number 1=PLT0805-5.0KACT-ND, Temperature Coefficient=5ppm/°C, Tolerance=0.05%, Voltage Rating=100V
R8A R8B: library part "1k Ohm 0.01% (0805) 1/8W", "RNCF Precision Thin Film Chip Resistor 0805 Size 1K Ohm 0.01% 0.125 W 5 ppm/°C 2-Pin SMD T/R", Case Code (Imperial)=0805, Case Code (Metric)=2012, Manufacturer="Stackpole Electronics", Manufacturer Part Number=RNCF0805TKY1K00, Max Operating Temperature=155°C, Max Power Dissipation=125mW, Min Operating Temperature=-55°C, Resistance=1kR, Resistor Type="Thin Film", Supplier Part Number 1=RNCF0805TKY1K00CT-ND, Temperature Coefficient=5ppm/°C, Tolerance=0.01%
R9A R9B: library part "14.3k Ohm 0.1% (0805)", "RES 14.3 KOHMS 0.1% 1/5W 0805", Manufacturer="TE Connectivity", Manufacturer Part Number=RQ73C2A14K3BTD, Supplier Part Number 1=A139868CT-ND
R10A R10B: library part "1.6k Ohm 0.05% (0805)", "Res Thin Film 0805 1.6K Ohm 0.05% 1/8W ±10ppm/°C Molded SMD SMD Punched Carrier T/R", Case Code (Imperial)=0805, Case Code (Metric)=2012, Manufacturer=Panasonic, Manufacturer Part Number=ERA-6ARW162V, Max Operating Temperature=155°C, Max Power Dissipation=125mW, Min Operating Temperature=-55°C, Package Quantity=5000, Resistance=1.6kR, Resistor Type="Thin Film,Metal Film", Supplier Part Number 1=P1.6KBSCT-ND, Temperature Coefficient=10ppm/°C, Tolerance=0.05%, Voltage Rating=100V
R11A R11B R21A R21B: library part "100k Ohm 0.01% (1206)", "100 kOhms ±0.01% 0.333W, 1/3W Chip Resistor 1206 (3216 Metric) Anti-Sulfur, Moisture Resistant Thin Film", Manufacturer="Vishay Sfernice", Manufacturer Part Number=P2TC1206D1003LNTA, Supplier Part Number 1=716-P2TC1206D1003LNTACT-ND
R12A R12B R15A R15B R17A R17B R18A R18B: library part "1k Ohm 0.01% (1206)", "RNCF Precision Thin Film Chip Resistor 1206 Size 1K Ohm 0.01% 0.25 W 5 ppm/°C 2-Pin SMD T/R", Case Code (Imperial)=1206, Case Code (Metric)=3216, Manufacturer="Stackpole Electronics", Manufacturer Part Number=RNCF1206TKY1K00, Max Operating Temperature=155°C, Max Power Dissipation=250mW, Min Operating Temperature=-55°C, Resistance=1kR, Resistor Type="Thin Film", Supplier Part Number 1=RNCF1206TKY1K00CT-ND, Temperature Coefficient=5ppm/°C, Tolerance=0.01%
R13A R13B R19A R19B: library part "3.01k Ohm 0.01% (1206)", "1206 Thin Film Chip Resistor / 1206 SMD Resistor 0.05% 10PPM 3.01 Kohm", Case Code (Imperial)=1206, Case Code (Metric)=3216, Manufacturer=Panasonic, Manufacturer Part Number=ERA-8ARW3011V, Max Operating Temperature=155°C, Max Power Dissipation=250mW, Min Operating Temperature=-55°C, Resistance=3.01kR, Resistor Type="Thin Film", Supplier Part Number 1=P18821CT-ND, Temperature Coefficient=10ppm/°C, Tolerance=0.05%
R14A R14B R20A R20B: library part "1.5k Ohm 0.01% (1206)", "Thin Film Resistors - SMD 1/4W 1.5K Ohms 0.01% 1206 2ppm", Case Code (Imperial)=1206, Case Code (Metric)=3216, Manufacturer=Susumu, Manufacturer Part Number=RG3216L-152-L-T05, Max Operating Temperature=155°C, Max Power Dissipation=125mW, Min Operating Temperature=-55°C, Package Quantity=500, Power Rating=250mW, Resistance=1.5kR, Resistor Type="Thin Film", Supplier Part Number 1=408-1647-1-ND, Temperature Coefficient=2ppm/°C, Tolerance=0.01%, Voltage Rating=200V
R16A R16B: library part "1206 Resistor OMIT"
TP1A TP1B: library part "TPT - Black", "Black PC Test Point, Multipurpose Phosphor Bronze Silver Plating 0.063\" (1.60mm) Hole Diameter Mounting Type", Flammability Rating="UL94 V-0", Manufacturer="Keystone Electronics", Manufacturer Part Number=5011, Package Quantity=100, Supplier Part Number 1=36-5011-ND
U1A U1B: "IC OPAMP GP 10MHZ 8SOIC", Case/Package=R, Dual Supply Voltage=9V, Input Bias Current=3nA, Input Capacitance=6.25pF, Input Offset Voltage (Vos)=75uV, Input Voltage Noise Density="2.8nV/sqrt Hz", Manufacturer="Analog Devices", Manufacturer Part Number=AD8672ARZ, Max Dual Supply Voltage=15V, Max Operating Temperature=125°C, Max Supply Current=7mA, Max Supply Voltage=36V, Min Dual Supply Voltage=5V, Min Operating Temperature=-40°C, Min Supply Voltage=10V, Output Current per Channel=20mA, Package Quantity=98, Power Supply Rejection Ratio (PSRR)=130dB, Quiescent Current=3.5mA, Supplier Part Number 1=AD8672ARZ-ND, Voltage Gain=135.56dB
U2A U2B: library part OP37GSZ-REEL, "Op Amp Single Precision Amplifier ±22V 8-Pin SOIC N T/R", Case/Package=R, Input Bias Current=15nA, Input Offset Voltage (Vos)=30uV, Input Voltage Noise Density="3.8nV/sqrt Hz", Manufacturer="Analog Devices", Max Dual Supply Voltage=22V, Max Operating Temperature=85°C, Min Dual Supply Voltage=4V, Min Operating Temperature=-40°C, Operating Supply Current=5.67mA, Package Quantity=2500, Power Supply Rejection Ratio (PSRR)=114dB, Supplier Part Number 1=OP37GSZ-REELCT-ND, Voltage Gain=123.52dB
U3A U3B: "OP Amp Quad GP ±22V 16-Pin SOIC W", Case/Package=SOIC, Dual Supply Voltage=9V, Input Bias Current=30nA, Input Offset Voltage (Vos)=140uV, Manufacturer="Analog Devices / Linear Technology", Manufacturer Part Number=LT1125CSW#PBF, Max Dual Supply Voltage=22V, Max Operating Temperature=70°C, Min Dual Supply Voltage=4V, Min Operating Temperature=0°C, Operating Supply Current=2.3mA, Package Quantity=47, Power Supply Rejection Ratio (PSRR)=110dB, Supplier Part Number 1=LT1125CSW#PBF-ND, Voltage Gain=143.52dB

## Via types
v1: diameter 31, hole 15, Top Layer to Bottom Layer, tented both sides, 52 vias
v2: diameter 50, hole 28, Top Layer to Bottom Layer, 2 vias
v3: diameter 31, hole 15, Top Layer to Bottom Layer, 2 vias

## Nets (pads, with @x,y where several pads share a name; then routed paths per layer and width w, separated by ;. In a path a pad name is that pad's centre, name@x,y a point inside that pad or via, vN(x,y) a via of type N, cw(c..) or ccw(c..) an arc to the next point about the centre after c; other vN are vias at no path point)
+15: C1A.1 C1B.1 C3A.1 C3B.1 C12A.1 C12B.1 C14A.1 C14B.1 D1.2 D3A.2 D3B.2 K1A.1 K1B.1 U1A.8 U1B.8 U2A.7 U2B.7 U3A.4 U3B.4 | length 5268.6
  Top Layer w10: v1(2530,1980) U3B.4@2609.06,1980 ; v1(2530,3220) U3A.4@2609.06,3220 ; U2B.7@3800,1954.8 v1(3870,1954.8) ; U2A.7@3800,3194.8 v1(3870,3194.8) ; D3B.2@4081.5,2009.8 4503.58,2009.8 cw(c4503.58,1909.8) 4574.29,1980.51 K1B.1@4650,1904.8 ; D3A.2@4081.5,3249.8 4503.58,3249.8 cw(c4503.58,3149.8) 4574.29,3220.51 K1A.1@4650,3144.8 ; U1B.8@5148.58,1904.8 v3(5148.58,1950) ; U1A.8@5148.58,3144.8 v3(5148.58,3190)
  Top Layer w20: v1(6215,1310) v1(6215,1160) 6215,1056.07 ccw(c6315,1056.07) 6244.29,985.36 D1.2@6290,939.65 ; v1(6290,1310) v1(6290,1160) D1.2@6290,939.65 ; v1(6365,1310) v1(6365,1160) 6365,1056.07 cw(c6265,1056.07) 6335.71,985.36 D1.2@6290,939.65
  Layer 1 (+V) w10: v1(2524.51,1555) v1@2530.38,1560.87 ; v1(2524.51,2795) v1@2530.38,2800.87 ; v1(2530,1980) cw(c2460.78,1909.37) 2559.67,1909.37 2559.67,1631.58 ; v1(2530,3220) cw(c2460.78,3149.37) 2559.67,3149.37 2559.67,2871.58 ; v1(3870,1954.8) 3870,2016.72 cw(c3938.28,2016.72) 3890,2065 ; v1(3870,3194.8) 3870,3256.72 cw(c3938.28,3256.72) 3890,3305 ; K1B.1@4650,1904.8 4650,2015.55 cw(c4741.15,2015.55) 4676.7,2080 ; K1A.1@4650,3144.8 4650,3255.55 cw(c4741.15,3255.55) 4676.7,3320 ; 4787.67,2012.47 ccw(c4799.21,2024.01) 4799.21,2007.69 4932.29,2007.69 cw(c4932.29,1947.29) 4975,1990 4985.71,1979.29 ccw(c5056.42,2050) 5056.42,1950 v3(5148.58,1950) ; 4787.67,3252.47 ccw(c4799.21,3264.01) 4799.21,3247.69 4932.29,3247.69 cw(c4932.29,3187.29) 4975,3230 4985.71,3219.29 ccw(c5056.42,3290) 5056.42,3190 v3(5148.58,3190)
  Bottom Layer w10: C14B.1@2482.09,1555 v1(2524.51,1555) ; C14A.1@2482.09,2795 v1(2524.51,2795) ; v1(3870,1954.8) 3875,1954.8 C3B.1@3950,2029.8 ; v1(3870,3194.8) ccw(c3870,3206.87) 3878.54,3198.34 C3A.1@3950,3269.8 ; v3(5148.58,1950) C1B.1@5148.58,2005 ; v3(5148.58,3190) C1A.1@5148.58,3245
  other v1: 6215,1235 6290,1235 6365,1235
-15: C2A.1 C2B.1 C5A.1 C5B.1 C15A.1 C15B.1 C16A.2 C16B.2 D2.1 U1A.4 U1B.4 U2A.4 U2B.4 U3A.13 U3B.13 | length 3936.1
  Top Layer w10: U3B.13@2990.94,1980 v1(3080,1980) ; U3A.13@2990.94,3220 v1(3080,3220) ; v1(3510,1854.8) U2B.4@3580,1854.8 ; v1(3510,3094.8) U2A.4@3580,3094.8 ; v1(4928.58,1710) U1B.4@4928.58,1754.8 ; v1(4928.58,2950) U1A.4@4928.58,2994.8
  Top Layer w20: v1(6535,1310) v1(6535,1160) 6535,1056.07 ccw(c6635,1056.07) 6564.29,985.36 D2.1@6610,939.65 ; v1(6610,1310) v1(6610,1160) D2.1@6610,939.65 ; v1(6685,1310) v1(6685,1160) 6685,1056.07 cw(c6585,1056.07) 6655.71,985.36 D2.1@6610,939.65
  Layer 2 (-V) w10: v1(3080,1980) cw(c3177.69,1993.27) 3108,2063 3164.98,2119.98 ccw(c3128.79,2156.21) v1@3180,2156.21 ; v1(3080,3220) cw(c3177.69,3233.27) 3108,3303 3164.98,3359.98 ccw(c3128.79,3396.21) v1@3180,3396.21 ; 3137.09,2360 v1(3180,2360) ; 3137.09,3600 v1(3180,3600) ; 3505,1750 ccw(c3492.93,1762.07) 3510,1762.07 v1(3510,1854.8) ; 3510,3010 v1(3510,3094.8) ; 4875,1625 4906.37,1656.37 ccw(c4852.73,1710) v1(4928.58,1710) ; 4875,2865 4906.37,2896.37 ccw(c4852.73,2950) v1(4928.58,2950)
  Bottom Layer w10: v1(3080,1980) cw(c3177.69,1993.27) 3108,2063 3164.98,2119.98 ccw(c3128.79,2156.21) 3180,2156.21 v1(3180,2360) C15B.1@3137.09,2360 ; v1(3080,3220) cw(c3177.69,3233.27) 3108,3303 3164.98,3359.98 ccw(c3128.79,3396.21) 3180,3396.21 v1(3180,3600) C15A.1@3137.09,3600 ; v1(3510,1854.8) 3510,1841.22 ccw(c3610,1841.22) 3539.29,1770.51 C5B.1@3580,1729.8 ; v1(3510,3094.8) 3510,3081.22 ccw(c3610,3081.22) 3539.29,3010.51 C5A.1@3580,2969.8 ; C2B.1@4928.58,1590 v1(4928.58,1710) ; C2A.1@4928.58,2830 v1(4928.58,2950)
  other v1: 6535,1235 6610,1235 6685,1235 3179.51,2160 3179.51,3400
"DCPD In A_n": J2.3 R17A.1 R21A.2 | length 1636.4
  Top Layer w12.64: J2.3@831,2600 908,2600 ccw(c908.08,2870.33) 1099.21,2679.16 1099.27,2679.22 1380.15,2960.1 cw(c2028.84,2311.49) 2028.84,3228.82 2056.27,3228.82 ccw(c2056.27,3246.24) 2068.59,3233.92 ccw(c2063.03,3239.48) 2070.89,3239.48 cw(c2078.75,3239.48) 2073.19,3245.04 2083.2,3255.05 cw(c2100,3238.25) R21A.2@2100,3262.01 cw(c2100,3238.25) 2116.8,3255.05 2126.81,3245.04 cw(c2121.25,3239.48) 2129.11,3239.48 ccw(c2136.97,3239.48) 2131.41,3233.92 2132.81,3232.52 ccw(c2141.75,3241.46) 2141.75,3228.82 2170.1,3228.82 ccw(c2170.1,3241.46) 2179.04,3232.52 ccw(c2170.1,3241.46) 2182.74,3241.46 2182.74,3244.48 cw(c2202.66,3244.48) 2188.57,3258.57 R17A.1@2202.01,3272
